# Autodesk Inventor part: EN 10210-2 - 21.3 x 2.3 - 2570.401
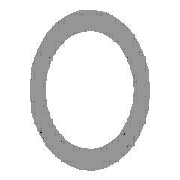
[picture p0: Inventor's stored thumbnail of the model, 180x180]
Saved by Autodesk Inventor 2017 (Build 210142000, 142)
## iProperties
Created: 2017-11
Part Number: EN 10210-2 - 21.3 x 2.3 - 2570.401
Material: Steel, Mild
Description: Pipe
Document SubType Name: Modeling
Standard: DIN
Designer: iusti
Standard Revision: 2006-07
Standards Organization: DIN
Language: en-US
Size Designation: 21.3 x 2.3
Categories: <MemberInstance><Categories><Category DisplayName="Structural Shapes" InternalName="089c4875-fa83-4c05-b084-43b9cc11f5ed" Mnemonic="GRDR"><CategoryParameter Dis
Stock Number: 21.3 x 2.3
Density: 7.85 g/cm^3
Appearance: Semi-Polished
_CCFamilyMember: 1
_CCFamilyDisplayName: DIN EN 10210-2 - Pipe
_FrameMemberDoc: Frame Member File
_Version: 15.0.0
_GetPNFromCC: 1
IsCustomPart: 1
Author: iusti
G_L: 2570.401 mm
G_W: 21.300 mm
G_H: 21.300 mm
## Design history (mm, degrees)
node "Start plane"
node "End plane"
sketch "Sketch"
  geometry: C1 r 8.35 at (0, 0); C2 r 10.65 at (0, 0); 2 further points
  constraints: 3 coincident, 2 centre point
  dimensions: "d0" = 21.3 diameter of C2 (= G_H); "d1" = 2.3 radial gap between concentric circles of C2 C1 (= G_T)
extrude "Body" new body sketch "Sketch" stored distance "d2" = 2570.40077 (= G_L); taper "d3" = 0 deg
node "Driven Length"
  sketch "Sketch3"
    geometry: L1 (0, 0)-(10, 0) reference
    constraints: 2 end point, 1 horizontal
  workplane "Work Plane3"
  sketch "Sketch4"
    geometry: L1 (-2, 0)-(12, 0) reference; L2 (-2, 2570.401)-(12, 2570.401) reference
    dimensions: "d7" = 2570.40077 distance between parallel lines of L1 L2 (derived)
body "Solid1"
other parameters: "G_H" = 21.3 [user parameter; used in 1 equation term], "G_T" = 2.3 [user parameter; used in 1 equation term], "G_L" = 2570.40077 (= d7) [user parameter; used in 1 equation term], "G_OFFSET_START" = 0 [user parameter; used in 1 equation term], "G_OFFSET_END" = 0 [user parameter; used in 1 equation term], "d4" = 0 (computed from G_OFFSET_START), "d5" = 2570.40077 (= G_OFFSET_END + B_L), "B_L" = 2570.40077 [user parameter; used in 1 equation term], "d6" = 90 deg
